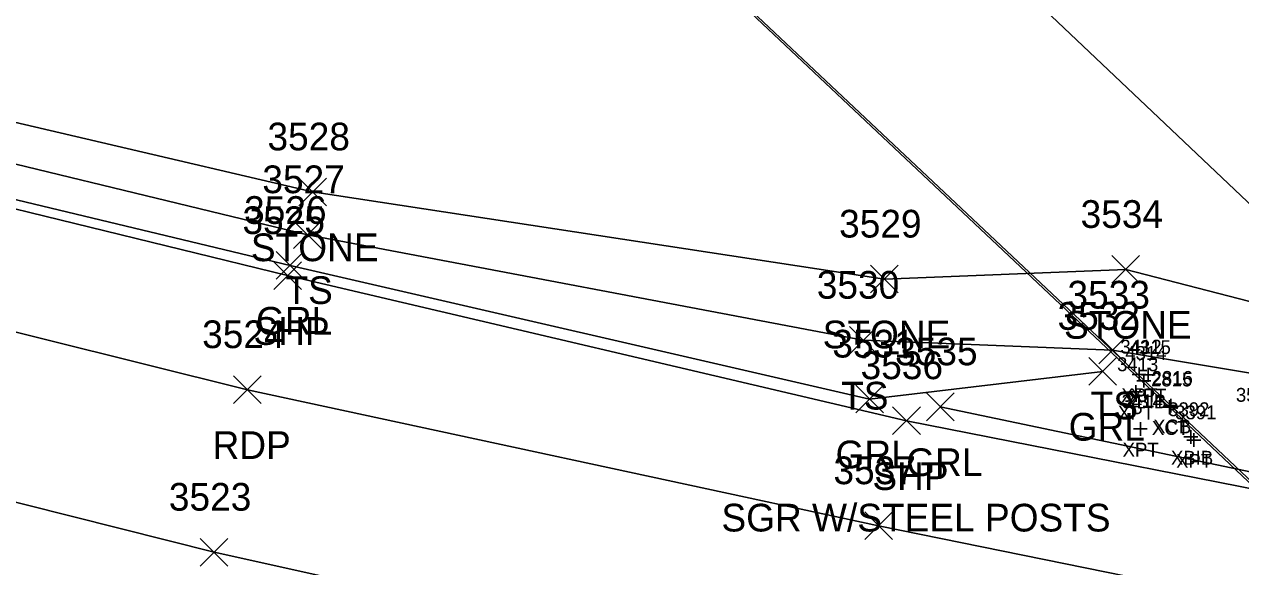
# Model space of a CAD drawing. Extents: x 1647574 to 1652703, y 212895 to 228670.
# Drawn here: x 1648808.6 to 1648896.4, y 227168.5 to 227207.7 of the extents above; entities that cross this region are included whole.
import ezdxf

# ---------------------------------------------------------------- set-up
doc = ezdxf.new("R2010")
doc.units = 0
for name, color, linetype in [('B_A', 7, 'Continuous'), ('B_I', 7, 'Continuous'), ('B_TIC', 7, 'Continuous'), ('BDC', 7, 'Continuous'), ('BELB', 7, 'Continuous'), ('L_A', 7, 'Continuous'), ('L_I', 7, 'Continuous'), ('L_TIC', 7, 'Continuous'), ('LASF', 7, 'Continuous'), ('LELB', 7, 'Continuous'), ('P_A', 7, 'Continuous'), ('P_I', 7, 'Continuous'), ('P_TIC', 7, 'Continuous'), ('PET', 7, 'Continuous'), ('PRC', 7, 'Continuous'), ('PSP', 7, 'Continuous'), ('R_A', 7, 'Continuous'), ('R_C', 7, 'Continuous'), ('R_I', 7, 'Continuous'), ('R_TIC', 7, 'Continuous'), ('RGR', 7, 'Continuous')]:
    doc.layers.add(name, color=color, linetype=linetype)

msp = doc.modelspace()

# ---------------------------------------------------------------- linework, layer by layer
at = {"layer": 'B_TIC'}
for p, q in [((1648889.025, 227182.421), (1648889.1, 227182.421)), ((1648889.377, 227181.967), (1648889.452, 227181.967)), ((1648889.69, 227182.389), (1648889.766, 227182.389)), ((1648888.785, 227181.152), (1648888.861, 227181.152)), ((1648891.234, 227180.054), (1648891.31, 227180.054)), ((1648891.308, 227180.165), (1648891.383, 227180.165)), ((1648889.119, 227178.484), (1648889.194, 227178.484)), ((1648892.758, 227177.904), (1648892.834, 227177.904)), ((1648892.981, 227177.68), (1648893.057, 227177.68))]:
    msp.add_line(p, q, dxfattribs=at)
for points in [[(1648889.021, 227181.921), (1648889.021, 227182.921)], [(1648889.687, 227181.889), (1648889.687, 227182.889)], [(1648888.521, 227182.421), (1648889.521, 227182.421)], [(1648888.873, 227181.967), (1648889.873, 227181.967)], [(1648889.187, 227182.389), (1648890.187, 227182.389)], [(1648889.373, 227181.467), (1648889.373, 227182.467)], [(1648888.282, 227181.152), (1648889.282, 227181.152)], [(1648888.782, 227180.652), (1648888.782, 227181.652)], [(1648890.731, 227180.054), (1648891.731, 227180.054)], [(1648890.804, 227180.165), (1648891.804, 227180.165)], [(1648891.231, 227179.554), (1648891.231, 227180.554)], [(1648891.304, 227179.665), (1648891.304, 227180.665)], [(1648888.615, 227178.484), (1648889.615, 227178.484)], [(1648889.115, 227177.984), (1648889.115, 227178.984)], [(1648892.755, 227177.404), (1648892.755, 227178.404)], [(1648892.255, 227177.904), (1648893.255, 227177.904)], [(1648892.478, 227177.68), (1648893.478, 227177.68)], [(1648892.978, 227177.18), (1648892.978, 227178.18)]]:
    msp.add_lwpolyline(points, dxfattribs=at)
at = {"layer": 'BDC'}
for points in [[(1648650.624, 227406.773), (1648690.525, 227369.254), (1648733.472, 227328.732), (1648776.312, 227288.32), (1648833.664, 227234.301), (1648891.231, 227180.054), (1648955.856, 227118.961), (1649002.635, 227075.018), (1649045.277, 227034.596)], [(1648651.076, 227406.804), (1648690.742, 227369.256), (1648733.458, 227328.853), (1648776.322, 227288.427), (1648833.713, 227234.413), (1648891.304, 227180.165), (1648955.952, 227119.198), (1649002.814, 227075.033), (1649045.282, 227034.879)]]:
    msp.add_lwpolyline(points, dxfattribs=at)
at = {"layer": 'BELB'}
msp.add_lwpolyline([(1648676.128, 227401.909), (1648716.738, 227364.514), (1648759.552, 227324.27), (1648803.456, 227283.214), (1648860.317, 227229.513), (1648917.836, 227175.012), (1648982.231, 227114.435), (1649029.643, 227069.952), (1649071.001, 227030.272)], dxfattribs=at)
at = {"layer": 'L_TIC'}
for points in [[(1648828.377, 227194.595), (1648830.377, 227196.595)], [(1648830.377, 227194.595), (1648828.377, 227196.595)], [(1648828.006, 227191.504), (1648830.006, 227193.504)], [(1648830.006, 227191.504), (1648828.006, 227193.504)], [(1648887.064, 227188.998), (1648889.064, 227190.998)], [(1648889.064, 227188.998), (1648887.064, 227190.998)], [(1648869.643, 227188.301), (1648871.643, 227190.301)], [(1648871.643, 227188.301), (1648869.643, 227190.301)], [(1648868.112, 227183.885), (1648870.112, 227185.885)], [(1648870.112, 227183.885), (1648868.112, 227185.885)], [(1648886.117, 227183.175), (1648888.117, 227185.175)], [(1648888.117, 227183.175), (1648886.117, 227185.175)]]:
    msp.add_lwpolyline(points, dxfattribs=at)
at = {"layer": 'LASF'}
msp.add_lwpolyline([(1648591.009, 227270.343), (1648624.693, 227258.455), (1648664.933, 227242.862), (1648702.926, 227233.816), (1648737.154, 227219.4), (1648772.089, 227211.83), (1648798.883, 227202.714), (1648829.377, 227195.595), (1648870.643, 227189.301), (1648888.064, 227189.998), (1648910.238, 227184.26), (1648945.065, 227174.552), (1648988.129, 227167.991), (1649019.013, 227162.278), (1649093.93, 227148.389), (1649131.468, 227140.127), (1649155.823, 227137.226), (1649206.951, 227127.276), (1649258.232, 227116.863), (1649289.141, 227114.771), (1649313.58, 227109.451)], dxfattribs=at)
at = {"layer": 'LELB'}
msp.add_lwpolyline([(1648597.273, 227264.486), (1648633.73, 227250.634), (1648664.389, 227240.318), (1648701.872, 227228.729), (1648735.461, 227216.545), (1648770.192, 227206.754), (1648796.996, 227200.241), (1648829.006, 227192.504), (1648869.112, 227184.885), (1648887.117, 227184.175), (1648909.076, 227180.513), (1648944.404, 227172.664), (1648985.415, 227160.185), (1649015.972, 227155.751), (1649030.56, 227151.792), (1649075.874, 227142.707), (1649094.964, 227142.334), (1649128.793, 227137.178), (1649163.599, 227126.992), (1649206.12, 227120.023), (1649254.696, 227110.714), (1649288.497, 227104.847), (1649312.044, 227099.384)], dxfattribs=at)
at = {"layer": 'P_TIC'}
for points in [[(1648826.571, 227188.553), (1648828.571, 227190.553)], [(1648828.571, 227188.553), (1648826.571, 227190.553)], [(1648823.663, 227180.318), (1648825.663, 227182.318)], [(1648825.663, 227180.318), (1648823.663, 227182.318)], [(1648871.239, 227178.077), (1648873.239, 227180.077)], [(1648873.239, 227178.077), (1648871.239, 227180.077)], [(1648869.225, 227170.495), (1648871.225, 227172.495)], [(1648871.225, 227170.495), (1648869.225, 227172.495)], [(1648821.259, 227168.584), (1648823.259, 227170.584)], [(1648823.259, 227168.584), (1648821.259, 227170.584)]]:
    msp.add_lwpolyline(points, dxfattribs=at)
at = {"layer": 'PET'}
msp.add_lwpolyline([(1648582.821, 227256.084), (1648618.147, 227242.999), (1648661.462, 227228.082), (1648697.31, 227216.445), (1648732, 227205.65), (1648767.283, 227195.85), (1648794.922, 227188.715), (1648824.663, 227181.318), (1648870.225, 227171.495), (1648904.553, 227164.504), (1648941.404, 227157.321), (1648982.588, 227149.559), (1649013.451, 227143.774), (1649051.482, 227136.017), (1649092.559, 227128.28), (1649129.41, 227121.264), (1649164.129, 227114.968), (1649203.067, 227107.319), (1649253.119, 227097.953), (1649285.33, 227091.532), (1649309.805, 227086.858)], dxfattribs=at)
at = {"layer": 'PRC'}
msp.add_lwpolyline([(1648578.474, 227245.088), (1648614.144, 227232.377), (1648658.376, 227217.212), (1648693.17, 227205.447), (1648728.772, 227194.614), (1648764.162, 227184.595), (1648791.485, 227177.326), (1648822.259, 227169.584), (1648868.208, 227159.379), (1648902.01, 227152.53), (1648938.677, 227144.922), (1648979.678, 227137.482), (1649011.638, 227131.497), (1649049.006, 227124.369), (1649090.363, 227116.947), (1649126.936, 227110.347), (1649164.154, 227103.487), (1649199.467, 227096.77), (1649251.628, 227086.358), (1649284.276, 227080.21), (1649307.757, 227075.596)], dxfattribs=at)
at = {"layer": 'PSP'}
msp.add_lwpolyline([(1648480.186, 227300.935), (1648523.095, 227287.235), (1648552.393, 227275.528), (1648583.82, 227263.797), (1648620.778, 227250.204), (1648663.69, 227235.815), (1648700.093, 227224.251), (1648734.52, 227213.948), (1648769.769, 227204.03), (1648796.828, 227197.07), (1648827.571, 227189.553), (1648872.239, 227179.077), (1648906.708, 227172.293), (1648943.109, 227165.503), (1648984.425, 227157.969), (1649015.263, 227151.943), (1649051.882, 227144.802), (1649094.443, 227136.72), (1649131.243, 227129.788), (1649164.299, 227122.927), (1649204.314, 227115.136), (1649254.536, 227105.699), (1649286.332, 227099.339), (1649311.67, 227094.73)], dxfattribs=at)
at = {"layer": 'R_TIC'}
for points in [[(1648826.747, 227189.287), (1648828.747, 227191.287)], [(1648828.747, 227189.287), (1648826.747, 227191.287)], [(1648885.4, 227181.638), (1648887.4, 227183.638)], [(1648887.4, 227181.638), (1648885.4, 227183.638)], [(1648868.576, 227179.639), (1648870.576, 227181.639)], [(1648870.576, 227179.639), (1648868.576, 227181.639)], [(1648873.676, 227179.08), (1648875.676, 227181.08)], [(1648875.676, 227179.08), (1648873.676, 227181.08)]]:
    msp.add_lwpolyline(points, dxfattribs=at)
at = {"layer": 'RGR'}
for points in [[(1648566.499, 227274.336), (1648584.93, 227265.187), (1648621.098, 227251.014), (1648663.82, 227236.679), (1648700.169, 227224.812), (1648734.661, 227214.696), (1648770.018, 227205.103), (1648796.736, 227197.709), (1648827.747, 227190.287), (1648869.576, 227180.639), (1648886.4, 227182.638)], [(1648874.676, 227180.08), (1648907.143, 227173.269), (1648943.277, 227166.367), (1648984.701, 227158.6), (1649014.789, 227152.98), (1649051.86, 227145.733), (1649094.582, 227137.658), (1649131.359, 227130.713), (1649164.131, 227124.406), (1649204.957, 227116.676), (1649254.392, 227107.302), (1649286.862, 227101.106), (1649311.642, 227096.214)]]:
    msp.add_lwpolyline(points, dxfattribs=at)

# ---------------------------------------------------------------- texts
at = {"layer": 'B_A'}
for s, p in [('XPT', (1648887.742, 227180.421)), ('XBIB', (1648887.944, 227179.967)), ('XPT', (1648888.407, 227180.389)), ('XPT', (1648887.502, 227179.152)), ('XCB', (1648890.041, 227178.165)), ('XCT', (1648889.951, 227178.054)), ('XPT', (1648887.836, 227176.484)), ('XBIB', (1648891.326, 227175.904)), ('XPT', (1648891.698, 227175.68))]:
    msp.add_text(s, height=1, dxfattribs=at).set_placement(p)
at = {"layer": 'B_I'}
for s, p in [('3412', (1648887.675, 227183.921)), ('4314', (1648888.027, 227183.467)), ('4315', (1648888.34, 227183.889)), ('3413', (1648887.436, 227182.652)), ('2816', (1648889.931, 227181.665)), ('2815', (1648889.885, 227181.554)), ('3414', (1648887.769, 227179.984)), ('3553', (1648896.013, 227180.444)), ('3392', (1648891.125, 227179.404)), ('3391', (1648891.631, 227179.18))]:
    msp.add_text(s, height=1, dxfattribs=at).set_placement(p)
at = {"layer": 'L_A'}
for s, p in [('STONE', (1648824.92, 227190.595)), ('TS', (1648827.415, 227187.504)), ('STONE', (1648883.607, 227184.998)), ('STONE', (1648866.187, 227184.301)), ('TS', (1648867.521, 227179.885)), ('TS', (1648885.527, 227179.175))]:
    msp.add_text(s, height=2, dxfattribs=at).set_placement(p)
at = {"layer": 'L_I'}
for s, p in [('3528', (1648826.117, 227198.595)), ('3527', (1648825.746, 227195.504)), ('3534', (1648884.804, 227192.998)), ('3529', (1648867.376, 227192.301)), ('3530', (1648865.765, 227187.885)), ('3533', (1648883.857, 227187.175))]:
    msp.add_text(s, height=2, dxfattribs=at).set_placement(p)
at = {"layer": 'P_A'}
for s, p in [('SHP', (1648825.106, 227184.553)), ('RDP', (1648822.152, 227176.318)), ('SHP', (1648869.775, 227174.077))]:
    msp.add_text(s, height=2, dxfattribs=at).set_placement(p)
at = {"layer": 'P_I'}
for s, p in [('3525', (1648824.311, 227192.553)), ('3524', (1648821.404, 227184.318)), ('3536', (1648868.924, 227182.077)), ('3537', (1648866.966, 227174.495)), ('3523', (1648819, 227172.584))]:
    msp.add_text(s, height=2, dxfattribs=at).set_placement(p)
at = {"layer": 'R_A'}
for p in [(1648825.29, 227185.287), (1648883.943, 227177.638), (1648867.119, 227175.639), (1648872.219, 227175.08)]:
    msp.add_text('GRL', height=2, dxfattribs=at).set_placement(p)
at = {"layer": 'R_C'}
msp.add_text('SGR W/STEEL POSTS', height=2, dxfattribs=at).set_placement((1648858.881, 227171.08))
at = {"layer": 'R_I'}
for s, p in [('3526', (1648824.432, 227193.287)), ('3532', (1648883.14, 227185.638)), ('3531', (1648866.883, 227183.639)), ('3535', (1648871.416, 227183.08))]:
    msp.add_text(s, height=2, dxfattribs=at).set_placement(p)

doc.saveas('drawing.dxf')
